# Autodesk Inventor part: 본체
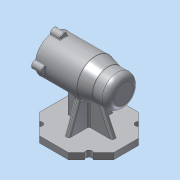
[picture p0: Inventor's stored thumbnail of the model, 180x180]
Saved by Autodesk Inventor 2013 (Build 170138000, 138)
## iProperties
Created: 2019-12
Part Number: 본체
Material: 알루미늄 6061
Document SubType Name: Modeling
Designer: Administrator
Density: 2.71 g/cm^3
Mass: 734.419 g
Surface Area: 723.811 cm^2
Volume: 271.003 cm^3
Author: Administrator
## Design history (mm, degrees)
sketch "스케치1"
  geometry: L1 (-56, 0)-(56, 0); L2 (-56, 0)-(-56, 25); L3 (-56, 25)-(-31, 25); L4 (-31, 25)-(-11, 30); L5 (-11, 30)-(56, 30); L6 (56, 0)-(56, 30); L7 (-47, 16)-(-43, 16); L8 (-43, 16)-(-43, 17.5); L9 (-43, 17.5)-(-25, 17.5); L10 (-25, 17.5)-(-25, 21); L11 (-25, 21)-(-13, 21); L12 (-13, 21)-(-13, 24); L13 (-13, 24)-(41, 24); L14 (41, 24)-(41, 21); L15 (41, 21)-(56, 21); L16 (-47, 16)-(-47, 10.5); L17 (-47, 10.5)-(-50, 10.5); L18 (-50, 10.5)-(-50, 0); 2 further points
  constraints: 36 end point, 11 perpendicular, 2 horizontal, 2 parallel, 2 point on line, 1 coincident, 1 midpoint
  dimensions: "d7" = 112 distance of L1.start L1.end; "d10" = 25 distance of L2.end L3.end; "d11" = 45 horizontal distance of L4.end L2.end; "d13" = 60 diameter of L5 L1; "d14" = 50 diameter of L3 L1; "d16" = 32 diameter of L7 L1; "d17" = 35 diameter of L9 L1; "d18" = 4 distance of L7.start L7.end; "d19" = 18 distance of L8.end L9.end; "d20" = 12 distance of L10.end L11.end; "d21" = 42 diameter of L11 L1; "d22" = 54 distance of L12.end L13.end; "d23" = 48 diameter of L13 L1; "d24" = 42 diameter of L15 L1; "d25" = 15 distance of L14.end L15.end; "d26" = 21 diameter of L17 L1; "d27" = 3 distance from line of L16.end L18
revolve "회전1" sketch "스케치1" stored, may be unused: angle "d28" = 90 deg
node "작업 평면1"
sketch "스케치2"
  geometry: L1 (-23.196, 56)-(23.196, 56); L2 (23.196, 56)-(59.473, 19.723); L3 (59.473, 19.723)-(59.473, -19.723); L4 (59.473, -19.723)-(23.196, -56); L5 (23.196, -56)-(-23.196, -56); L6 (-23.196, -56)-(-56, -23.196); L7 (-56, -23.196)-(-56, 23.196); L8 (-56, 23.196)-(-23.196, 56); C1 r 56 at (0, 0); 2 further points
  constraints: 16 end point, 4 tangent, 3 perpendicular, 3 vertical alignment, 1 centre point, 1 coincident, 1 horizontal, 1 midpoint, 1 vertical
  dimensions: "d32" = 56 distance from line of point (0, 0) L1; "d33" = 112 diameter of C1; "d35" = 56 distance from line of point (0, 0) L5; "d36" = 56 distance from line of point (0, 0) L7
extrude "돌출1" join sketch "스케치2" distance "d42" = 10; taper "d43" = 0 deg
sketch "스케치3"
  geometry: L1 (23.196, -56)-(56, -23.196) reference; L2 (56, -23.196)-(56, 23.196) reference; L3 (56, 23.196)-(23.196, 56) reference; L4 (-23.196, 56)-(-59.473, 19.723) reference; L5 (-59.473, -19.723)-(-23.196, -56) reference; C1 r 5 at (-39.598, 39.598); C2 r 5 at (39.598, 39.598); C3 r 5 at (39.598, -39.598); C4 r 5 at (-39.598, -39.598); A1 r 56 centre (0, 0) between (-39.598, 39.598) and (39.598, 39.598); 1 further point
  constraints: 5 centre point, 4 point on circle, 3 equal radius, 2 midpoint, 2 point on line, 1 coincident, 1 tangent
  dimensions: "d44" = 10 diameter of C1
extrude "돌출2" cut sketch "스케치3" distance "d46" = 10; taper "d47" = 0 deg
sketch "스케치4"
  geometry: C1 r 30 at (0, 0) reference; C2 r 21 at (0, 0)
  constraints: 1 centre point, 1 coincident
  dimensions: "d48" = 42 diameter of C2
extrude "돌출3" cut sketch "스케치4" distance "d50" = 15; taper "d51" = 0 deg
sketch "스케치5"
  geometry: C1 r 21 at (0, 0) reference; C2 r 24 at (0, 0)
  constraints: 1 centre point, 1 coincident
  dimensions: "d52" = 48 diameter of C2
extrude "돌출4" cut sketch "스케치5" distance "d54" = 54; taper "d55" = 0 deg
sketch "스케치6"
  geometry: C1 r 24 at (0, 0) reference; C2 r 21 at (0, 0)
  constraints: 1 centre point, 1 coincident
  dimensions: "d56" = 42 diameter of C2
extrude "돌출5" cut sketch "스케치6" distance "d58" = 12; taper "d59" = 0 deg
sketch "스케치7"
  geometry: C1 r 21 at (0, 0) reference; C2 r 17.5 at (0, 0)
  constraints: 1 centre point, 1 coincident
  dimensions: "d60" = 35 diameter of C2
extrude "돌출6" cut sketch "스케치7" distance "d62" = 18; taper "d63" = 0 deg
sketch "스케치8"
  geometry: C1 r 17.5 at (0, 0) reference; C2 r 16 at (0, 0)
  constraints: 1 centre point, 1 coincident
  dimensions: "d64" = 32 diameter of C2
extrude "돌출7" cut sketch "스케치8" distance "d66" = 4; taper "d67" = 0 deg
sketch "스케치9"
  geometry: C1 r 16 at (0, 0) reference; C2 r 10.5 at (0, 0)
  constraints: 1 centre point, 1 coincident
  dimensions: "d68" = 21 diameter of C2
extrude "돌출8" cut sketch "스케치9" distance "d70" = 3; taper "d71" = 0 deg
sketch "스케치10"
  geometry: L1 (-56, -25)-(-31, -25) reference; L2 (-11, -30)-(56, -30) reference; L3 (-23.196, -70)-(23.196, -70) reference; L4 (-36.062, -70)-(-23.196, -70) reference; L5 (-59.473, -70)-(-43.134, -70) reference; L6 (-43.134, -70)-(-34.598, -70) reference; L7 (-41.473, -70)-(-21.587, -27.353); L8 (23.196, -70)-(36.062, -70) reference; L9 (34.598, -70)-(43.134, -70) reference; L10 (43.134, -70)-(43.134, -80) reference; L11 (56, -80)-(43.134, -80) reference; L12 (56, -80)-(56, -70) reference; L13 (43.134, -70)-(56, -70) reference; L14 (43.134, -70)-(56, -70) reference; L15 (31, -30)-(31, -70); L16 (-41.473, -70)-(31, -70); L17 (-21.587, -27.353)-(-20.425, -24.861); L18 (-20.425, -24.861)-(31, -24.861); L19 (31, -24.861)-(31, -30); 1 further point
  constraints: 12 end point, 3 point on line, 2 perpendicular, 1 collinear, 1 parallel, 1 vertical
  dimensions: "d72" = 25 distance of L12.end L15.end; "d73" = 18 distance of L5.start L7.start; "d74" = 115 deg angle of L5 L7
extrude "돌출9" join sketch "스케치10" stored distance "d75" = 8; taper "d76" = 0 deg
sketch "스케치11"
  geometry: L1 (-70, 36.062)-(-70, 23.196) reference; L2 (-70, 43.134)-(-70, 34.598) reference; L3 (-70, 56)-(-70, 43.134) reference; L4 (-70, 23.196)-(-70, -23.196) reference; L5 (-70, -23.196)-(-70, -36.062) reference; L6 (-70, -34.598)-(-70, -43.134) reference; L7 (-70, -43.134)-(-70, -56) reference; L8 (-23.234, 18.979)-(-70, 36); L9 (-23.234, -18.979)-(-70, -36); A1 r 30 centre (0, 0) between (-23.234, 18.979) and (-23.234, -18.979) reference; 1 further point
  constraints: 4 end point, 2 point on circle, 2 point on line
  dimensions: "d77" = 20 distance of L3.start L8.end; "d78" = 20 distance of L7.end L9.end; "d79" = 110 deg angle of L3 L8; "d80" = 110 deg angle of L7 L9
feature "리브1" sketch "스케치11" dims "d81" = 1, "d82" = 8, "d83" = 0, "d84" = 0, "d85" = 1, "d86" = 1
sketch "스케치12"
  geometry: L1 (-70, 23.196)-(-70, -23.196) reference; L2 (-70, -23.196)-(-70, -36.062) reference; L3 (-70, -34.598)-(-70, -43.134) reference; L4 (-70, -43.134)-(-70, -56) reference; L5 (-23.234, -18.979)-(-70, -36); 2 further points
  constraints: 2 end point, 1 point on line, 2 other
  dimensions: "d87" = 20 distance of L4.end L5.end; "d88" = 110 deg angle of L4 L5
feature "리브2" sketch "스케치12" dims "d89" = 1, "d90" = 8, "d91" = 0, "d92" = 0, "d93" = 1, "d94" = 1
sketch "스케치13"
  geometry: C1 r 21 at (0, 0) reference; C2 r 30 at (0, 0); C3 r 6 at (0, 30); C4 r 6 at (-30, 0); C5 r 6 at (0, -30); C6 r 6 at (30, 0); A1 r 30 centre (0, 0) between (0, 30) and (30, 0) reference
  constraints: 5 centre point, 4 point on circle, 3 equal radius, 2 horizontal alignment, 2 vertical alignment, 1 coincident
  dimensions: "d95" = 60 diameter of C2; "d97" = 12 diameter of C3
extrude "돌출10" join sketch "스케치13" distance "d98" = 16; taper "d99" = 0 deg
sketch "스케치14"
  geometry: A1 r 6 centre (30, 30) between (35.97, 29.4) and (24.03, 29.4) reference; A2 r 6 centre (0, 0) between (0.6, 5.97) and (0.6, -5.97) reference; A3 r 6 centre (30, -30) between (24.03, -29.4) and (35.97, -29.4) reference; A4 r 6 centre (60, 0) between (59.4, -5.97) and (59.4, 5.97) reference; 4 further points
  constraints: 4 coincident
hole "구멍1" sketch "스케치14" at (30, 30), (0, 0), (30, -30), (60, 0) diameter "d100" = 3.242; stored, may be unused: countersink angle "d104" = 90 deg, drill point angle "d106" = 118 deg; dims "d101" = 8, "d102" = 4, "d103" = 2, "d105" = 11
fillet "모깎기1" dims "d107" = 1
fillet "모깎기2" dims "d108" = 1
fillet "모깎기3" dims "d109" = 1
fillet "모깎기4" dims "d110" = 1
fillet "모깎기5" dims "d111" = 3
fillet "모깎기6" dims "d112" = 3
fillet "모깎기7" dims "d113" = 3
fillet "모깎기8" dims "d114" = 3
fillet "모깎기9" dims "d115" = 3
fillet "모깎기10" dims "d116" = 3
fillet "모깎기11" dims "d117" = 3
fillet "모깎기12" dims "d118" = 10
fillet "모깎기13" dims "d119" = 3
chamfer "모따기1" distance "d120" = 1; stored, may be unused: second distance "d121" = 2, angle "d122" = 45 deg
fillet "모깎기14" dims "d123" = 3
fillet "모깎기15" dims "d124" = 3
fillet "모깎기16" dims "d125" = 0.3
fillet "모깎기17" dims "d126" = 0.3
node "작업 평면2"
sketch "스케치15"
  geometry: L1 (56, 6.771)-(56, 29.226) reference; L2 (56, 5.998)-(56, -5.998) reference; 3 further points
  constraints: 1 horizontal alignment, 1 midpoint, 1 other
  dimensions: "d128" = 41 distance from line of L1 point (15, 0)
feature "엠보싱1" sketch "스케치15" dims "d129" = 0.5, "d130" = 0
fillet "모깎기18" dims "d131" = 3
node "솔리드1"
node "투영된 루프1"
